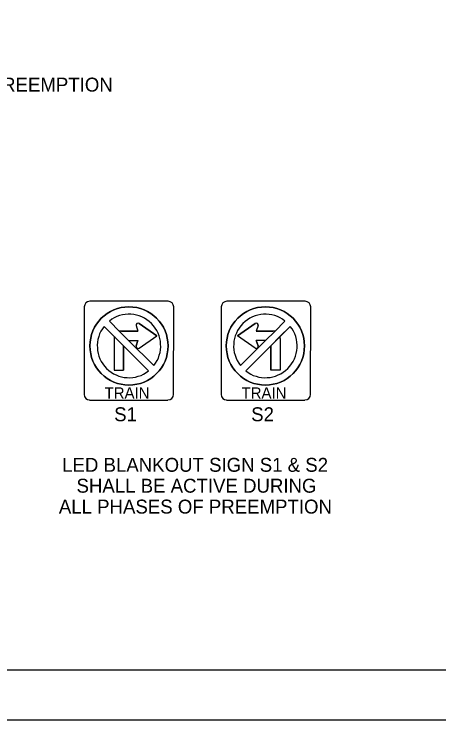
# Model space of a CAD drawing. Extents: x 0 to 680, y 0 to 551.
# Drawn here: x 509.1 to 594.6, y 0 to 141.9 of the extents above; entities that cross this region are included whole.
import ezdxf

# ---------------------------------------------------------------- set-up
doc = ezdxf.new("R2010")
doc.units = 0
for name, color, linetype in [('SG_P_Text', 7, 'Continuous'), ('SH_Border', 7, 'Continuous'), ('SH_Cut_Line', 7, 'Continuous'), ('SH_Data', 7, 'Continuous'), ('SH_Text', 7, 'Continuous'), ('SN_P_Signs', 7, 'Continuous')]:
    doc.layers.add(name, color=color, linetype=linetype)

msp = doc.modelspace()

# ---------------------------------------------------------------- linework, layer by layer
at = {"layer": 'SH_Border'}
msp.add_lwpolyline([(30, 430), (670, 430), (670, 10), (30, 10)], close=True, dxfattribs=at)
at = {"layer": 'SH_Cut_Line'}
msp.add_lwpolyline([(0, 0), (680, 0), (680, 440), (0, 440)], close=True, dxfattribs=at)
at = {"layer": 'SH_Data'}
for p, q in [((534.26, 79.71), (537.84, 77.25)), ((557.61, 79.71), (554.02, 77.25)), ((530.72, 78.19), (534.03, 78.19)), ((533.69, 79.29), (534.03, 78.19)), ((558.18, 79.29), (557.83, 78.19)), ((561.15, 78.19), (557.83, 78.19)), ((529.22, 76.69), (529.22, 70.31)), ((534.26, 74.78), (537.84, 77.25)), ((557.61, 74.78), (554.02, 77.25)), ((562.65, 76.69), (562.65, 70.31)), ((531.09, 75.25), (531.09, 70.31)), ((532.15, 76.31), (534.03, 76.31)), ((533.69, 75.2), (534.03, 76.31)), ((559.71, 76.31), (557.83, 76.31)), ((558.18, 75.2), (557.83, 76.31)), ((560.77, 75.25), (560.77, 70.31)), ((529.22, 70.31), (531.09, 70.31)), ((562.65, 70.31), (560.77, 70.31))]:
    msp.add_line(p, q, dxfattribs=at)
for points in [[(540.09, 84.19), (524.34, 84.19)], [(567.65, 84.19), (551.9, 84.19)], [(523.22, 83.06), (523.18, 65.45)], [(541.18, 65.45), (541.22, 83.06)], [(550.77, 83.06), (550.74, 65.45)], [(568.74, 65.45), (568.77, 83.06)], [(534.26, 74.78), (537.84, 77.25), (534.26, 79.71)], [(557.61, 74.78), (554.02, 77.25), (557.61, 79.71)], [(530.33, 78.13), (532.15, 76.31), (534.03, 76.31), (533.69, 75.2)], [(533.69, 79.29), (534.03, 78.19), (530.72, 78.19)], [(558.18, 79.29), (557.83, 78.19), (561.15, 78.19)], [(561.53, 78.13), (559.71, 76.31), (557.83, 76.31), (558.18, 75.2)], [(529.22, 76.69), (529.22, 70.31), (531.09, 70.31), (531.09, 75.25)], [(531.09, 75.25), (529.27, 77.07)], [(560.77, 75.25), (562.59, 77.07)], [(562.65, 76.69), (562.65, 70.31), (560.77, 70.31), (560.77, 75.25)], [(524.3, 64.32), (540.05, 64.32)], [(551.86, 64.32), (567.61, 64.32)]]:
    msp.add_lwpolyline(points, dxfattribs=at)
for centre, radius, start, end in [((524.34, 83.06), 1.12, 90, 180), ((540.09, 83.06), 1.12, 360, 90), ((551.9, 83.06), 1.12, 90, 180), ((567.65, 83.06), 1.12, 360, 90), ((534.04, 79.4), 0.375, 55.4837, 197.3618), ((534.04, 79.4), 0.375, 55.4837, 197.3618), ((557.82, 79.4), 0.375, 342.6382, 124.5163), ((557.82, 79.4), 0.375, 342.6382, 124.5163), ((530.72, 76.69), 1.5, 90, 105), ((530.72, 76.69), 1.5, 90, 105), ((561.15, 76.69), 1.5, 75, 90), ((561.15, 76.69), 1.5, 75, 90), ((530.72, 76.69), 1.5, 165, 180), ((530.72, 76.69), 1.5, 165, 180), ((561.15, 76.69), 1.5, 0, 15), ((561.15, 76.69), 1.5, 0, 15), ((534.04, 75.09), 0.375, 162.6382, 304.5163), ((534.04, 75.09), 0.375, 162.6382, 304.5163), ((557.82, 75.09), 0.375, 235.4837, 17.3618), ((557.82, 75.09), 0.375, 235.4837, 17.3618), ((524.3, 65.45), 1.12, 180, 270), ((540.05, 65.45), 1.12, 270, 360), ((551.86, 65.45), 1.12, 180, 270), ((567.61, 65.45), 1.12, 270, 360)]:
    msp.add_arc(centre, radius, start, end, dxfattribs=at)
at = {"layer": 'SN_P_Signs'}
for p, q in [((527.21, 79.13), (536.16, 70.18)), ((564.65, 79.13), (555.7, 70.18))]:
    msp.add_line(p, q, dxfattribs=at)
for points in [[(530.33, 78.13), (528.27, 80.19)], [(561.53, 78.13), (563.59, 80.19)], [(527.21, 79.13), (529.27, 77.07)], [(537.22, 71.24), (532.15, 76.31), (530.33, 78.13)], [(554.64, 71.24), (559.71, 76.31), (561.53, 78.13)], [(564.65, 79.13), (562.59, 77.07)], [(529.27, 77.07), (531.09, 75.25), (536.16, 70.18)], [(562.59, 77.07), (560.77, 75.25), (555.7, 70.18)]]:
    msp.add_lwpolyline(points, dxfattribs=at)
for centre in [(532.22, 75.19), (559.65, 75.19)]:
    msp.add_circle(centre, 7.87, dxfattribs=at)
for centre, radius, start, end in [((532.22, 75.19), 7.87, 360, 180), ((559.65, 75.19), 7.87, 0, 180), ((532.22, 75.19), 6.38, 321.7563, 128.2437), ((532.22, 75.19), 6.38, 321.7563, 128.2437), ((559.65, 75.19), 6.38, 51.7563, 218.2437), ((559.65, 75.19), 6.38, 51.7563, 218.2437), ((532.22, 75.19), 6.38, 141.7563, 308.2437), ((532.22, 75.19), 6.38, 141.7563, 308.2437), ((559.65, 75.19), 6.38, 231.7563, 38.2437), ((559.65, 75.19), 6.38, 231.7563, 38.2437), ((532.22, 75.19), 7.87, 180, 360), ((559.65, 75.19), 7.87, 180, 0)]:
    msp.add_arc(centre, radius, start, end, dxfattribs=at)

# ---------------------------------------------------------------- texts
at = {"layer": 'SG_P_Text'}
msp.add_text('PEDESTRIAN PHASES OPERATING DURING THE PREEMPTION', height=2.8, dxfattribs=at).set_placement((415.57, 126.35))
at = {"layer": 'SH_Data'}
for p in [(527.31, 64.62), (554.86, 64.62)]:
    msp.add_text('TRAIN', height=2.25, rotation=360, dxfattribs=at).set_placement(p)
at = {"layer": 'SH_Text'}
for s, p in [('S1', (529.24, 60.06)), ('S2', (556.8, 60.06)), ('LED BLANKOUT SIGN S1 & S2', (518.78, 49.89)), ('SHALL BE ACTIVE DURING', (521.66, 45.69)), ('ALL PHASES OF PREEMPTION', (518.11, 41.49))]:
    msp.add_text(s, height=2.8, dxfattribs=at).set_placement(p)

doc.saveas('drawing.dxf')
